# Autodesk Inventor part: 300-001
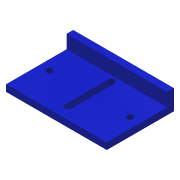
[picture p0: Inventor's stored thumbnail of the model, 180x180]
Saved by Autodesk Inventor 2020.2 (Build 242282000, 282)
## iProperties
Created: 2014-01
Part Number: 300-001
Material: Ogólny
Document SubType Name: Modeling
Designer: F.Stasiak
Density: 1 g/cm^3
Appearance: Niebieska - farba ścienna - lśniąca
Manager: www.cadconsulting.pl
Company: Fabian Stasiak CAD Consulting
Author: F.Stasiak
Subject: Zbiór ćwiczeń. Autodesk Inventor 2020. Kurs podstawowy
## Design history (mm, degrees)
sketch "Szkic1"
  geometry: L1 (-75, 10)-(75, 10); L2 (75, 10)-(75, 0); L3 (75, 0)-(-75, 0); L4 (-75, 0)-(-75, 10); 2 further points
  constraints: 8 end point, 2 equal length, 1 coincident, 1 midpoint, 1 parallel, 1 vertical
  dimensions: "d0" = 150 distance of L2.end L3.end; "d1" = 10 distance of L1.end L2.end
extrude "Wyciągnięcie proste1" new body sketch "Szkic1" distance "d2" = 100; taper "d3" = 0 deg
sketch "Szkic2"
  geometry: L1 (0, 0)-(150, 0) reference; L2 (0, 0)-(0, -100) reference; L3 (150, 0)-(150, -100) reference; L4 (150, -10)-(0, -10); 1 further point
  constraints: 2 end point, 2 point on line, 1 perpendicular
  dimensions: "d4" = 10 distance between parallel lines of L4 L1
extrude "Wyciągnięcie proste2" join sketch "Szkic2" distance "d5" = 20; taper "d6" = 0 deg
sketch "Szkic3"
  geometry: L1 (0, 100)-(150, 100) reference; L2 (0, 0)-(0, 100) reference; L3 (15, 50)-(135, 50); L4 (150, 0)-(150, 100) reference; 4 further points
  constraints: 3 midpoint, 2 end point, 1 perpendicular, 1 point on line, 1 vertical alignment
  dimensions: "d7" = 120 distance of L3.start L3.end
hole "Otwór1" sketch "Szkic3" at (15, 50), (135, 50) diameter "d9" = 10; stored, may be unused: countersink angle "d13" = 90 deg, drill point angle "d15" = 118 deg; dims "d10" = 6, "d11" = 4, "d12" = 2, "d14" = 8
sketch "Szkic4"
  geometry: L1 (150, 0)-(150, 100) reference; L2 (0, 100)-(150, 100) reference; L3 (75, 82.5)-(75, 17.5); L4 (70, 82.5)-(70, 17.5); L5 (80, 17.5)-(80, 82.5); A1 r 5 centre (75, 82.5) between (80, 82.5) and (70, 82.5); A2 r 5 centre (75, 17.5) between (70, 17.5) and (80, 17.5); 4 further points
  constraints: 8 end point, 4 point on circle, 4 tangent, 3 midpoint, 2 centre point, 2 parallel, 1 horizontal alignment, 1 point on line
  dimensions: "d16" = 65 distance of L3.start L3.end; "d17" = 10 diameter of A2
extrude "Wyciągnięcie proste3" cut sketch "Szkic4" extent not by distance; stored distance "d18" = 10; taper "d19" = 0 deg
node "Bryła1"
